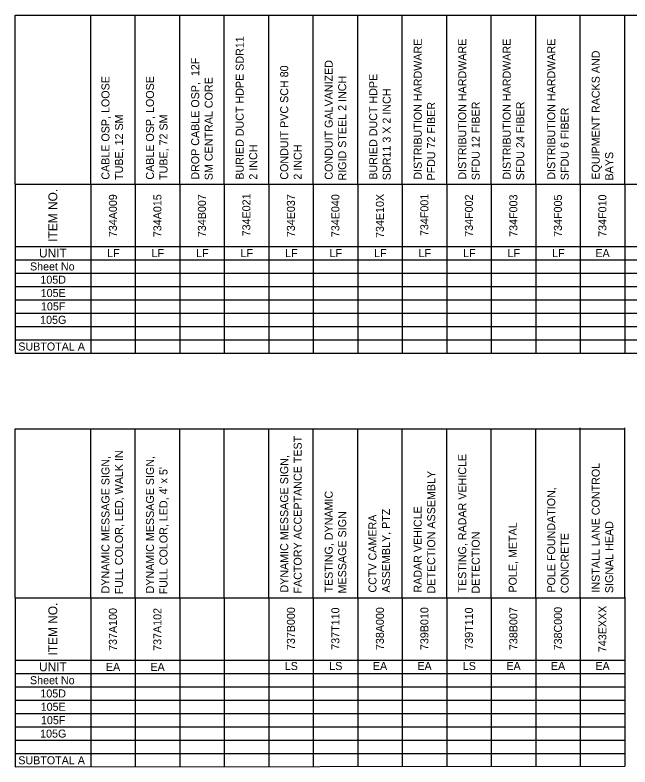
# Model space of a CAD drawing. Extents: x 5.9 to 40, y 1.1 to 19.8.
# Drawn here: x 5.91 to 19.72, y 1.17 to 18.07 of the extents above; entities that cross this region are included whole.
import ezdxf

# ---------------------------------------------------------------- set-up
doc = ezdxf.new("R2010")
doc.units = 0

msp = doc.modelspace()

# ---------------------------------------------------------------- linework, layer by layer
for p, q in [((5.905, 18.066), (28.611, 18.066)), ((5.905, 14.266), (5.905, 18.066)), ((7.605, 14.266), (7.605, 18.066)), ((8.605, 14.266), (8.605, 18.066)), ((9.605, 14.266), (9.605, 18.066)), ((10.605, 14.266), (10.605, 18.066)), ((11.605, 14.266), (11.605, 18.066)), ((12.605, 14.266), (12.605, 18.066)), ((13.605, 14.266), (13.605, 18.066)), ((13.605, 14.266), (13.605, 18.066)), ((14.605, 14.266), (14.605, 18.066)), ((15.605, 14.266), (15.605, 18.066)), ((16.605, 14.266), (16.605, 18.066)), ((17.605, 14.266), (17.605, 18.066)), ((18.605, 14.266), (18.605, 18.066)), ((19.605, 14.266), (19.605, 18.066)), ((5.905, 14.266), (28.611, 14.266)), ((5.905, 14.266), (5.905, 12.866)), ((7.605, 14.266), (7.605, 12.866)), ((8.605, 14.266), (8.605, 12.866)), ((9.605, 14.266), (9.605, 12.866)), ((10.605, 14.266), (10.605, 12.866)), ((11.605, 14.266), (11.605, 12.866)), ((12.605, 14.266), (12.605, 12.866)), ((13.605, 14.266), (13.605, 12.866)), ((14.605, 14.266), (14.605, 12.866)), ((15.605, 14.266), (15.605, 12.866)), ((16.605, 14.266), (16.605, 12.866)), ((17.605, 14.266), (17.605, 12.866)), ((18.605, 14.266), (18.605, 12.866)), ((19.605, 14.266), (19.605, 12.866)), ((5.905, 12.866), (28.611, 12.866)), ((5.905, 12.866), (5.905, 10.466)), ((7.605, 12.866), (7.605, 10.466)), ((8.605, 12.866), (8.605, 10.466)), ((9.605, 12.866), (9.605, 10.466)), ((10.605, 12.866), (10.605, 10.466)), ((11.605, 12.866), (11.605, 10.466)), ((12.605, 12.866), (12.605, 10.466)), ((13.605, 12.866), (13.605, 10.466)), ((14.605, 12.866), (14.605, 10.466)), ((15.605, 12.866), (15.605, 10.466)), ((16.605, 12.866), (16.605, 10.466)), ((17.605, 12.866), (17.605, 10.466)), ((18.605, 12.866), (18.605, 10.466)), ((19.605, 12.866), (19.605, 10.466)), ((5.905, 12.566), (28.611, 12.566)), ((5.905, 12.266), (28.611, 12.266)), ((5.905, 11.966), (28.611, 11.966)), ((5.905, 11.666), (28.611, 11.666)), ((5.905, 11.366), (28.611, 11.366)), ((5.905, 11.066), (28.611, 11.066)), ((5.905, 10.766), (28.611, 10.766)), ((5.905, 10.466), (28.611, 10.466)), ((5.905, 8.766), (19.605, 8.766)), ((5.905, 4.966), (5.905, 8.766)), ((7.605, 4.966), (7.605, 8.766)), ((8.605, 4.966), (8.605, 8.766)), ((9.605, 4.966), (9.605, 8.766)), ((10.605, 4.966), (10.605, 8.766)), ((11.605, 4.966), (11.605, 8.766)), ((12.605, 4.966), (12.605, 8.766)), ((13.605, 4.966), (13.605, 8.766)), ((14.605, 4.966), (14.605, 8.766)), ((15.605, 4.966), (15.605, 8.766)), ((16.605, 4.966), (16.605, 8.766)), ((17.605, 4.966), (17.605, 8.766)), ((18.605, 4.986), (18.605, 8.786)), ((19.605, 4.986), (19.605, 8.786)), ((5.905, 4.966), (19.605, 4.966)), ((5.905, 4.966), (5.905, 3.566)), ((7.605, 4.966), (7.605, 3.566)), ((8.605, 4.966), (8.605, 3.566)), ((9.605, 4.966), (9.605, 3.566)), ((10.605, 4.966), (10.605, 3.566)), ((11.605, 4.966), (11.605, 3.566)), ((12.605, 4.966), (12.605, 3.566)), ((13.605, 4.966), (13.605, 3.566)), ((14.605, 4.966), (14.605, 3.566)), ((15.605, 4.966), (15.605, 3.566)), ((16.605, 4.966), (16.605, 3.566)), ((17.605, 4.966), (17.605, 3.566)), ((18.605, 4.986), (18.605, 3.586)), ((19.605, 4.986), (19.605, 3.586)), ((5.905, 3.566), (19.605, 3.566)), ((5.905, 3.566), (5.905, 1.166)), ((7.605, 3.566), (7.605, 1.166)), ((8.605, 3.566), (8.605, 1.166)), ((9.605, 3.566), (9.605, 1.166)), ((10.605, 3.566), (10.605, 1.166)), ((11.605, 3.566), (11.605, 1.166)), ((12.605, 3.566), (12.605, 1.166)), ((13.605, 3.566), (13.605, 1.166)), ((14.605, 3.566), (14.605, 1.166)), ((15.605, 3.566), (15.605, 1.166)), ((16.605, 3.566), (16.605, 1.166)), ((17.605, 3.566), (17.605, 1.166)), ((18.605, 3.586), (18.605, 1.186)), ((19.605, 3.586), (19.605, 1.186)), ((5.905, 3.266), (19.605, 3.266)), ((5.905, 2.966), (19.605, 2.966)), ((5.905, 2.666), (19.605, 2.666)), ((5.905, 2.366), (19.605, 2.366)), ((5.905, 2.066), (19.605, 2.066)), ((5.905, 1.766), (19.605, 1.766)), ((5.905, 1.466), (19.605, 1.466)), ((5.905, 1.166), (19.605, 1.186))]:
    msp.add_line(p, q)

# ---------------------------------------------------------------- texts
for s, height, rotation, p in [('BURIED DUCT HDPE SDR11 ', 0.18, 90, (11.044, 14.366)), ('DISTRIBUTION HARDWARE ', 0.18, 90, (15.045, 14.366)), ('DISTRIBUTION HARDWARE ', 0.18, 90, (16.044, 14.366)), ('DISTRIBUTION HARDWARE ', 0.18, 90, (17.044, 14.366)), ('DISTRIBUTION HARDWARE ', 0.18, 90, (18.044, 14.366)), ('EQUIPMENT RACKS AND ', 0.18, 90, (19.044, 14.366)), ('DROP CABLE OSP,  12F ', 0.18, 90, (10.044, 14.366)), ('CONDUIT PVC SCH 80', 0.18, 90, (12.044, 14.366)), ('CONDUIT GALVANIZED ', 0.18, 90, (13.044, 14.366)), ('BURIED DUCT HDPE ', 0.18, 90, (14.044, 14.366)), ('CABLE OSP, LOOSE ', 0.18, 90, (8.027, 14.366)), ('CABLE OSP, LOOSE ', 0.18, 90, (9.027, 14.366)), ('SM CENTRAL CORE', 0.18, 90, (10.347, 14.355)), ('RIGID STEEL 2 INCH', 0.18, 90, (13.347, 14.347)), ('SDR11 3 X 2 INCH', 0.18, 90, (14.347, 14.355)), ('PFDU 72 FIBER', 0.18, 90, (15.346, 14.347)), ('SFDU 12 FIBER', 0.18, 90, (16.347, 14.355)), ('SFDU 24 FIBER', 0.18, 90, (17.347, 14.355)), ('SFDU 6 FIBER', 0.18, 90, (18.347, 14.355)), ('TUBE, 12 SM', 0.18, 90, (8.331, 14.36)), ('TUBE, 72 SM', 0.18, 90, (9.331, 14.36)), ('2 INCH', 0.18, 90, (11.347, 14.366)), ('2 INCH', 0.18, 90, (12.347, 14.366)), ('BAYS', 0.18, 90, (19.347, 14.348)), ('ITEM NO.', 0.2, 90, (6.855, 12.971)), ('734A015', 0.18, 90, (9.194, 13.074)), ('734E021', 0.18, 90, (11.194, 13.092)), ('734E040', 0.18, 90, (13.194, 13.075)), ('734E10X', 0.18, 90, (14.194, 13.056)), ('734F001', 0.18, 90, (15.194, 13.099)), ('734A009', 0.18, 90, (8.194, 13.075)), ('734B007', 0.18, 90, (10.194, 13.075)), ('734E037', 0.18, 90, (12.194, 13.075)), ('734F002', 0.18, 90, (16.194, 13.083)), ('734F003', 0.18, 90, (17.194, 13.082)), ('734F005', 0.18, 90, (18.194, 13.081)), ('734F010', 0.18, 90, (19.194, 13.082)), ('FACTORY ACCEPTANCE TEST', 0.18, 90, (12.347, 5.065)), ('DYNAMIC MESSAGE SIGN, ', 0.18, 90, (8.027, 5.066)), ('FULL COLOR, LED, WALK IN', 0.18, 90, (8.331, 5.046)), ('DYNAMIC MESSAGE SIGN, ', 0.18, 90, (9.027, 5.066)), ('DYNAMIC MESSAGE SIGN, ', 0.18, 90, (12.044, 5.086)), ('TESTING, RADAR VEHICLE ', 0.18, 90, (16.044, 5.086)), ('INSTALL LANE CONTROL ', 0.18, 90, (19.044, 5.086)), ("FULL COLOR, LED, 4' x 5'", 0.18, 90, (9.331, 5.046)), ('DETECTION ASSEMBLY', 0.18, 90, (15.347, 5.066)), ('TESTING, DYNAMIC ', 0.18, 90, (13.044, 5.086)), ('POLE FOUNDATION, ', 0.18, 90, (18.044, 5.086)), ('ASSEMBLY, PTZ', 0.18, 90, (14.331, 5.086)), ('RADAR VEHICLE ', 0.18, 90, (15.044, 5.086)), ('MESSAGE SIGN', 0.18, 90, (13.347, 5.067)), ('CCTV CAMERA ', 0.18, 90, (14.027, 5.086)), ('POLE, METAL', 0.18, 90, (17.179, 5.086)), ('SIGNAL HEAD', 0.18, 90, (19.347, 5.074)), ('DETECTION ', 0.18, 90, (16.347, 5.066)), ('CONCRETE', 0.18, 90, (18.347, 5.073)), ('ITEM NO.', 0.2, 90, (6.855, 3.671)), ('737B000', 0.18, 90, (12.194, 3.794)), ('737T110', 0.18, 90, (13.194, 3.801)), ('738A000', 0.18, 90, (14.194, 3.794)), ('739B010', 0.18, 90, (15.194, 3.794)), ('739T110', 0.18, 90, (16.194, 3.801)), ('738B007', 0.18, 90, (17.194, 3.794)), ('738C000', 0.18, 90, (18.195, 3.787)), ('743EXXX', 0.18, 90, (19.194, 3.747)), ('737A100', 0.18, 90, (8.194, 3.775)), ('737A102', 0.18, 90, (9.194, 3.776)), ('UNIT', 0.2, 360, (6.443, 3.318)), ('Sheet No', 0.18, 360, (6.241, 3.026)), ('SUBTOTAL A', 0.18, 360, (5.978, 1.226))]:
    msp.add_text(s, height=height, rotation=rotation).set_placement(p)
for s, height, p in [('UNIT', 0.2, (6.443, 12.618)), ('LF', 0.18, (7.974, 12.626)), ('LF', 0.18, (8.974, 12.626)), ('LF', 0.18, (9.974, 12.626)), ('LF', 0.18, (10.974, 12.626)), ('LF', 0.18, (11.974, 12.626)), ('LF', 0.18, (12.974, 12.626)), ('LF', 0.18, (13.974, 12.626)), ('LF', 0.18, (14.974, 12.626)), ('LF', 0.18, (15.974, 12.626)), ('LF', 0.18, (16.974, 12.626)), ('LF', 0.18, (17.974, 12.626)), ('EA', 0.18, (18.947, 12.626)), ('Sheet No', 0.18, (6.241, 12.326)), ('105D', 0.18, (6.475, 12.028)), ('105E', 0.18, (6.482, 11.728)), ('105F', 0.18, (6.488, 11.428)), ('105G', 0.18, (6.469, 11.126)), ('SUBTOTAL A', 0.18, (5.978, 10.526)), ('EA', 0.18, (7.947, 3.326)), ('EA', 0.18, (8.947, 3.326)), ('LS', 0.18, (11.967, 3.346)), ('LS', 0.18, (12.967, 3.346)), ('EA', 0.18, (13.947, 3.346)), ('EA', 0.18, (14.947, 3.346)), ('LS', 0.18, (15.967, 3.346)), ('EA', 0.18, (16.947, 3.346)), ('EA', 0.18, (17.947, 3.346)), ('EA', 0.18, (18.947, 3.346)), ('105D', 0.18, (6.475, 2.728)), ('105E', 0.18, (6.482, 2.428)), ('105F', 0.18, (6.488, 2.128)), ('105G', 0.18, (6.469, 1.826))]:
    msp.add_text(s, height=height).set_placement(p)

doc.saveas('drawing.dxf')
